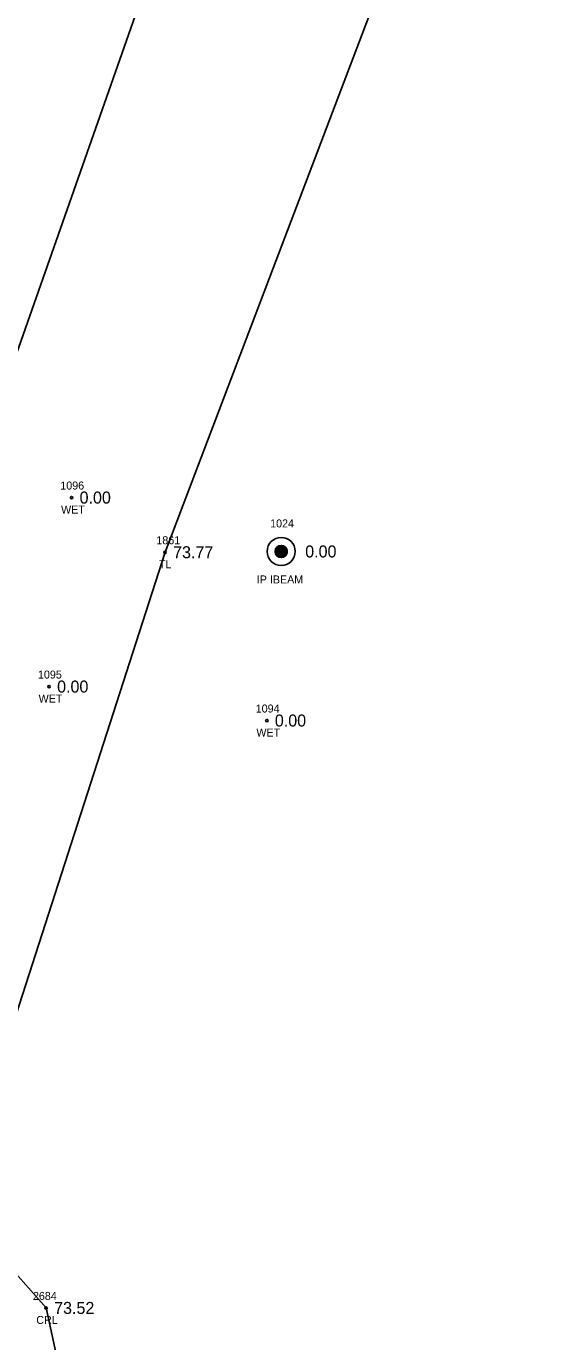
# Model space of a CAD drawing. Extents: x 2139392 to 2143384, y 505395 to 510520.
# Drawn here: x 2140780.9 to 2140845.2, y 508341.4 to 508505.7 of the extents above; entities that cross this region are included whole.
import ezdxf

# ---------------------------------------------------------------- set-up
doc = ezdxf.new("R2010")
doc.units = 0
for name, color, linetype in [('RD_EV_EX_Wetlands', 7, 'Continuous'), ('RD_EX_DV_Prop_txCode', 7, 'Continuous'), ('RD_EX_DV_PropPin', 7, 'Continuous'), ('RD_EX_H2O', 7, 'Continuous'), ('RD_EX_H2O_txCode', 7, 'Continuous'), ('RD_EX_H2O_WetLd_txCode', 7, 'Continuous'), ('RD_EX_TX_DV_Prop_ELEV', 7, 'Continuous'), ('RD_EX_TX_H2O_ELEV', 7, 'Continuous'), ('RD_EX_TX_H2O_WetLd_ELEV', 7, 'Continuous'), ('RD_EX_TX_VEG_ELEV', 7, 'Continuous'), ('RD_EX_VEG', 7, 'Continuous'), ('RD_EX_VEG_txCode', 7, 'Continuous'), ('RD_SMD_Locator', 7, 'Continuous')]:
    doc.layers.add(name, color=color, linetype=linetype)

msp = doc.modelspace()

# ---------------------------------------------------------------- linework, layer by layer
at = {"layer": 'RD_EV_EX_Wetlands'}
msp.add_line((2141075.3, 509306.14), (2140751.4, 508384.33), dxfattribs=at)
at = {"layer": 'RD_EX_DV_PropPin'}
for p, q in [((2140812.48, 508439.4), (2140812.48, 508440.82)), ((2140812.52, 508439.39), (2140812.52, 508440.83)), ((2140812.55, 508439.38), (2140812.55, 508440.84)), ((2140812.59, 508439.37), (2140812.59, 508440.85)), ((2140812.62, 508439.36), (2140812.62, 508440.86)), ((2140812.66, 508439.36), (2140812.66, 508440.86)), ((2140812.69, 508439.35), (2140812.69, 508440.87)), ((2140812.73, 508439.35), (2140812.73, 508440.87)), ((2140812.76, 508439.35), (2140812.76, 508440.87)), ((2140812.8, 508439.35), (2140812.8, 508440.87)), ((2140812.83, 508439.35), (2140812.83, 508440.87)), ((2140812.87, 508439.36), (2140812.87, 508440.86)), ((2140812.9, 508439.36), (2140812.9, 508440.86)), ((2140812.94, 508439.37), (2140812.94, 508440.85)), ((2140812.97, 508439.38), (2140812.97, 508440.84)), ((2140813.01, 508439.39), (2140813.01, 508440.83)), ((2140813.04, 508439.4), (2140813.04, 508440.82)), ((2140812.03, 508439.91), (2140812.03, 508440.31)), ((2140812.06, 508439.81), (2140812.06, 508440.41)), ((2140812.1, 508439.74), (2140812.1, 508440.48)), ((2140812.13, 508439.68), (2140812.13, 508440.54)), ((2140812.17, 508439.63), (2140812.17, 508440.58)), ((2140812.2, 508439.59), (2140812.2, 508440.62)), ((2140812.24, 508439.56), (2140812.24, 508440.66)), ((2140812.27, 508439.53), (2140812.27, 508440.69)), ((2140812.31, 508439.5), (2140812.31, 508440.72)), ((2140812.34, 508439.47), (2140812.34, 508440.74)), ((2140812.38, 508439.45), (2140812.38, 508440.77)), ((2140812.41, 508439.43), (2140812.41, 508440.78)), ((2140812.45, 508439.42), (2140812.45, 508440.8)), ((2140813.08, 508439.42), (2140813.08, 508440.8)), ((2140813.11, 508439.43), (2140813.11, 508440.78)), ((2140813.15, 508439.45), (2140813.15, 508440.77)), ((2140813.18, 508439.47), (2140813.18, 508440.74)), ((2140813.22, 508439.5), (2140813.22, 508440.72)), ((2140813.25, 508439.53), (2140813.25, 508440.69)), ((2140813.29, 508439.56), (2140813.29, 508440.66)), ((2140813.32, 508439.59), (2140813.32, 508440.62)), ((2140813.36, 508439.63), (2140813.36, 508440.58)), ((2140813.39, 508439.68), (2140813.39, 508440.54)), ((2140813.43, 508439.74), (2140813.43, 508440.48)), ((2140813.46, 508439.81), (2140813.46, 508440.41)), ((2140813.5, 508439.91), (2140813.5, 508440.31))]:
    msp.add_line(p, q, dxfattribs=at)
for radius in [1.75, 0.761]:
    msp.add_circle((2140812.76, 508440.11), radius, dxfattribs=at)
at = {"layer": 'RD_EX_H2O'}
msp.add_lwpolyline([(2140739.62, 508387.96), (2140740.93, 508386.48), (2140746.26, 508378.4), (2140760.93, 508371.03), (2140783.4, 508345.61), (2140795.83, 508288.39), (2140821, 508236), (2140860.19, 508250.22), (2140881.65, 508244.68), (2140916.39, 508224.49), (2140943.62, 508213.42), (2140932.23, 508147.43), (2140918.3, 508109.01), (2140923.7, 508051.95), (2140980.19, 508013.39), (2141009.38, 508052.91), (2141114.83, 508040.99)], dxfattribs=at)
at = {"layer": 'RD_EX_VEG'}
msp.add_lwpolyline([(2141197.74, 509262.45), (2141108.66, 509301.7), (2140947.3, 508831.92), (2140798.26, 508440.01), (2140718.9, 508193.9), (2140671.92, 508048.02), (2140772.34, 507989.74)], dxfattribs=at)
at = {"layer": 'RD_SMD_Locator'}
for centre in [(2140786.58, 508446.84), (2140798.26, 508440.01), (2140812.76, 508440.11), (2140783.77, 508423.23), (2140810.97, 508418.99), (2140783.4, 508345.61)]:
    msp.add_circle(centre, 0.15, dxfattribs=at)

# ---------------------------------------------------------------- texts
at = {"layer": 'RD_EX_DV_Prop_txCode'}
for s, p in [('1024', (2140811.38, 508443.11)), ('IP IBEAM', (2140809.71, 508436.11))]:
    msp.add_text(s, height=1, dxfattribs=at).set_placement(p)
at = {"layer": 'RD_EX_H2O_txCode'}
for s, p in [('2684', (2140781.75, 508346.61)), ('CRL', (2140782.17, 508343.61))]:
    msp.add_text(s, height=1, dxfattribs=at).set_placement(p)
at = {"layer": 'RD_EX_H2O_WetLd_txCode'}
for s, p in [('1096', (2140785.17, 508447.84)), ('WET', (2140785.27, 508444.84)), ('1095', (2140782.38, 508424.23)), ('WET', (2140782.46, 508421.23)), ('1094', (2140809.58, 508419.99)), ('WET', (2140809.66, 508416.99))]:
    msp.add_text(s, height=1, dxfattribs=at).set_placement(p)
at = {"layer": 'RD_EX_TX_DV_Prop_ELEV'}
msp.add_text('0.00', height=1.5, dxfattribs=at).set_placement((2140815.76, 508439.36))
at = {"layer": 'RD_EX_TX_H2O_ELEV'}
msp.add_text('73.52', height=1.5, dxfattribs=at).set_placement((2140784.4, 508344.86))
at = {"layer": 'RD_EX_TX_H2O_WetLd_ELEV'}
for p in [(2140787.58, 508446.09), (2140784.77, 508422.48), (2140811.97, 508418.24)]:
    msp.add_text('0.00', height=1.5, dxfattribs=at).set_placement(p)
at = {"layer": 'RD_EX_TX_VEG_ELEV'}
msp.add_text('73.77', height=1.5, dxfattribs=at).set_placement((2140799.26, 508439.26))
at = {"layer": 'RD_EX_VEG_txCode'}
for s, p in [('1861', (2140797.17, 508441.01)), ('TL', (2140797.49, 508438.01))]:
    msp.add_text(s, height=1, dxfattribs=at).set_placement(p)

doc.saveas('drawing.dxf')
